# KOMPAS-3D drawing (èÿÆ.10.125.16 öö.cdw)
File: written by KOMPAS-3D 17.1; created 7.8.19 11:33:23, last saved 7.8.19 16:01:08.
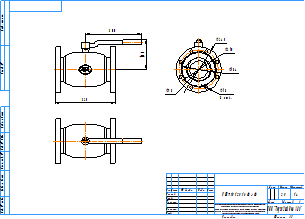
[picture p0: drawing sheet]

Sheet 1: A3, landscape

Title block, sheet 1: name: КШТ.10.125.16 Ф/Ф; material: Сталь 20  ГОСТ 1050-2013; mass: 25; sheets: 1; sheet format: A3; stored path: C:\Users\kka\KOMPAS_Work\Модели кранов для исследований\DN125\КШТ.10.125.16 СС.cdw

Views: Вид 1, Проекционный вид 2, Проекционный вид 3
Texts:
  kka
  adl
  Рама для чертежей
  Лит-Масса-Масштаб
  Материал-Предприятие
  Масштаб
  Изм.
  Лист
  № докум.
  Подп.
  Дата
  Лит.
  Разраб.
  Пров.
  Т.контр.
  Листов
  Внимание! Данный продукт является объектом авторского права ООО «Торговый Дом АДЛ».
  Запрещается изменение, копирование, распространение
  (в том числе путем копирования на другие сайты и ресурсы в Интернете)
  или любое иное использование информации и объектов без предварительного
  согласия правообладателя (ООО «Торговый Дом АДЛ»).
  Н.контр.
  Утв.
  ООО "Торговый дом АДЛ"
  Изменение
  Номер документа
  Подпись
  Обозначение документа
  Наименование изделия
  Масса изделия по ГОСТ 2.109-73
  Порядковый номер листа
  Общее количество листов в документе
  Характер работы, выполненной лицом, подписавшим документ
  Наименование или индекс предприятия, выпускающего документ
  Инв. № подл.
  Подп. и дата
  Взам. инв. №
  Инв. № дубл.
  Инвентарный номер подлинника по ГОСТ 2.501-68
  Подпись принявшего подлинник в отдел технической документации
  Инвентарный номер подлинника, взамен которого выпущен данный подлинник
  Инвентарный номер дубликата по ГОСТ 2.502-68
  Подпись принявшего дубликат в отдел технической документации
  Справ. №
  Перв. примен.
  Обозначение документа, взамен или на основании которого выпущен данный документ
  Обозначение документа, в котором впервые записан данный документ
  Подпись лица, копировавшего чертеж
  Обозначение формата листа
  !Рама для чертежа
Dimensions and other numbers on the sheet: 300; 160; 325; 98; 245; 210; 184; 18; 8 отв.; 1:4; 1; 25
